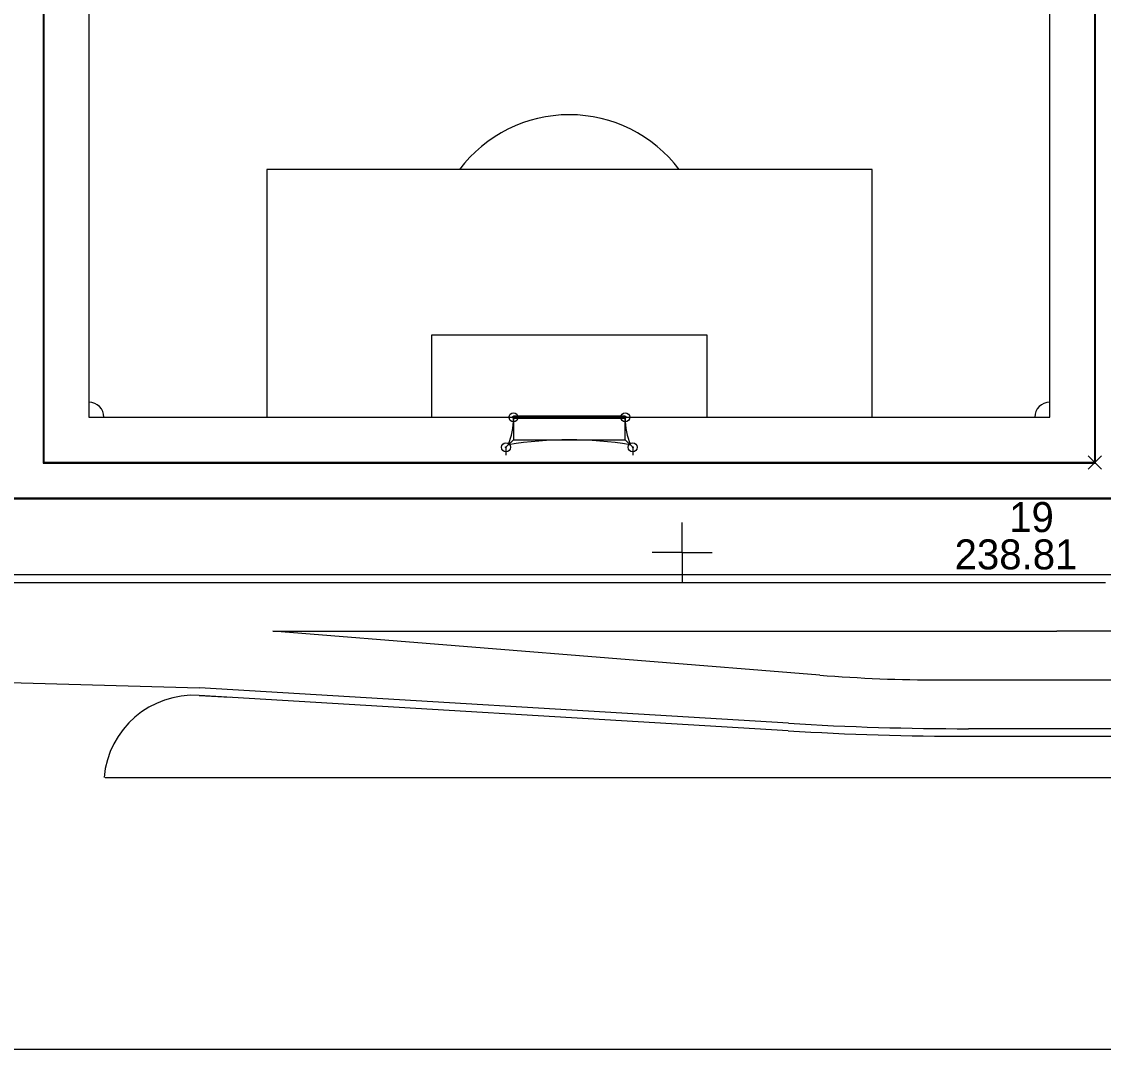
# Model space of a CAD drawing. Extents: x -264165 to -263575, y -1242333 to -1242036.
# Drawn here: x -264044 to -263971.9, y -1242333.1 to -1242264.6 of the extents above; entities that cross this region are included whole.
import ezdxf

# ---------------------------------------------------------------- set-up
doc = ezdxf.new("R2010")
doc.units = 0
for name, color, linetype in [('KFA_BODY_VYTYCOVAK', 7, 'Continuous'), ('KFA_HEKT_SIET_1-1000', 7, 'Continuous'), ('KFA_SITUACIA_DRS_VYTYCOVAK_SEDA', 7, 'Continuous'), ('RAM_NA_TLAC', 7, 'Continuous')]:
    doc.layers.add(name, color=color, linetype=linetype)

msp = doc.modelspace()

# ---------------------------------------------------------------- linework, layer by layer
at = {"layer": 'KFA_BODY_VYTYCOVAK'}
for p, q in [((-263972.962, -1242294.432), (-263972.078, -1242293.548)), ((-263972.078, -1242294.432), (-263972.962, -1242293.548))]:
    msp.add_line(p, q, dxfattribs=at)
at = {"layer": 'KFA_HEKT_SIET_1-1000'}
for q in [(-264000, -1242298), (-264002, -1242300), (-263998, -1242300), (-264000, -1242302)]:
    msp.add_line((-264000, -1242300), q, dxfattribs=at)
at = {"layer": 'KFA_SITUACIA_DRS_VYTYCOVAK_SEDA'}
for p, q in [((-264042.568, -1242187.932), (-264042.568, -1242294.032)), ((-264042.568, -1242187.932), (-264042.568, -1242294.032)), ((-264042.518, -1242187.982), (-264042.518, -1242293.982)), ((-263972.518, -1242293.982), (-263972.518, -1242187.982)), ((-263972.468, -1242294.032), (-263972.468, -1242187.932)), ((-263972.468, -1242294.032), (-263972.468, -1242187.932)), ((-264039.518, -1242190.982), (-264039.518, -1242290.982)), ((-263975.518, -1242290.982), (-263975.518, -1242190.982)), ((-263975.518, -1242290.982), (-263975.518, -1242190.982)), ((-263975.518, -1242290.982), (-263975.518, -1242190.982)), ((-263987.358, -1242274.482), (-264027.678, -1242274.482)), ((-264027.678, -1242274.482), (-264027.678, -1242290.982)), ((-263987.358, -1242274.482), (-264001.154, -1242274.482)), ((-263987.358, -1242290.982), (-263987.358, -1242274.482)), ((-263987.358, -1242290.982), (-263987.358, -1242274.482)), ((-264016.678, -1242290.982), (-264016.678, -1242285.482)), ((-264016.678, -1242285.482), (-263998.358, -1242285.482)), ((-264001.154, -1242285.482), (-263998.358, -1242285.482)), ((-263998.358, -1242285.482), (-263998.358, -1242290.982)), ((-263998.358, -1242285.482), (-263998.358, -1242290.982)), ((-264039.518, -1242290.982), (-263975.518, -1242290.982)), ((-264027.678, -1242290.982), (-264016.678, -1242290.982)), ((-264003.798, -1242290.922), (-264011.238, -1242290.922)), ((-264011.238, -1242290.982), (-264011.238, -1242292.482)), ((-264011.238, -1242291.042), (-264003.798, -1242291.042)), ((-264003.798, -1242291.042), (-264011.238, -1242291.042)), ((-264003.798, -1242292.482), (-264003.798, -1242290.982)), ((-264001.154, -1242290.982), (-263975.518, -1242290.982)), ((-264001.154, -1242290.982), (-263975.518, -1242290.982)), ((-263998.358, -1242290.982), (-263987.358, -1242290.982)), ((-263998.358, -1242290.982), (-263987.358, -1242290.982)), ((-264011.238, -1242292.482), (-264011.738, -1242292.982)), ((-264011.738, -1242292.982), (-264011.738, -1242293.499)), ((-264011.238, -1242292.482), (-264003.798, -1242292.482)), ((-264003.798, -1242292.482), (-264003.298, -1242292.982)), ((-264003.298, -1242292.982), (-264003.298, -1242293.499)), ((-264042.568, -1242294.032), (-263972.468, -1242294.032)), ((-264042.568, -1242294.032), (-263972.468, -1242294.032)), ((-264042.518, -1242293.982), (-263972.518, -1242293.982)), ((-263970.068, -1242296.432), (-264120.068, -1242296.432)), ((-263970.118, -1242296.382), (-264120.018, -1242296.382)), ((-263965.143, -1242296.432), (-264120.018, -1242296.432)), ((-263971.068, -1242301.482), (-264112.961, -1242301.482)), ((-264112.961, -1242301.982), (-263971.806, -1242301.982)), ((-263990.84, -1242308.161), (-264027.273, -1242305.232)), ((-264027.273, -1242305.232), (-263975.045, -1242305.232)), ((-263907.131, -1242305.232), (-263975.045, -1242305.232)), ((-264050.531, -1242308.482), (-264032.141, -1242309.015)), ((-263982.828, -1242308.482), (-263877.273, -1242308.482)), ((-263992.94, -1242311.872), (-264032.171, -1242309.514)), ((-264032.171, -1242309.514), (-264030.1, -1242309.638)), ((-263992.91, -1242311.373), (-264032.141, -1242309.015)), ((-263842.662, -1242311.732), (-263980.94, -1242311.732)), ((-263980.94, -1242312.232), (-263857.327, -1242312.232)), ((-264038.443, -1242314.982), (-263836.403, -1242314.982))]:
    msp.add_line(p, q, dxfattribs=at)
for centre, radius in [((-264011.238, -1242290.982), 0.3), ((-264003.798, -1242290.982), 0.3), ((-264011.238, -1242290.982), 0.06), ((-264011.238, -1242290.982), 0.055), ((-264003.798, -1242290.982), 0.06), ((-264003.798, -1242290.982), 0.055), ((-264011.738, -1242292.982), 0.3), ((-264011.738, -1242292.982), 0.03), ((-264011.738, -1242292.982), 0.0275), ((-264003.298, -1242292.982), 0.3), ((-264003.298, -1242292.982), 0.03), ((-264003.298, -1242292.982), 0.0275)]:
    msp.add_circle(centre, radius, dxfattribs=at)
for centre, radius, start, end in [((-264007.518, -1242279.982), 9.15, 36.94821, 143.05179), ((-264039.518, -1242290.982), 1, 0, 90), ((-263975.518, -1242290.982), 1, 90, 180), ((-264016.206, -1242291.024), 4.969, 338.83915, 359.78523), ((-263998.829, -1242291.024), 4.969, 180.21477, 201.16091), ((-264007.518, -1242317.192), 24.71, 80.55463, 99.44531), ((-263982.828, -1242208.482), 100, 265.40445, 270), ((-264032.531, -1242315.503), 6, 86.56019, 175.02052), ((-263980.94, -1242112.232), 199.5, 266.56019, 270), ((-263980.94, -1242112.232), 200, 266.56019, 270)]:
    msp.add_arc(centre, radius, start, end, dxfattribs=at)
at = {"layer": 'RAM_NA_TLAC'}
msp.add_lwpolyline([(-264165.158, -1242333.092), (-264165.158, -1242036.092), (-263955.158, -1242036.092), (-263575.158, -1242036.092), (-263575.158, -1242333.092), (-263955.158, -1242333.092)], close=True, dxfattribs=at)

# ---------------------------------------------------------------- texts
at = {"layer": 'KFA_BODY_VYTYCOVAK'}
for s, p in [('19', (-263978.221, -1242298.633)), ('238.81', (-263981.856, -1242301.119))]:
    msp.add_text(s, height=2, dxfattribs=at).set_placement(p)

doc.saveas('drawing.dxf')
